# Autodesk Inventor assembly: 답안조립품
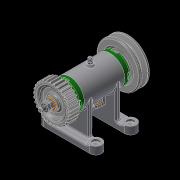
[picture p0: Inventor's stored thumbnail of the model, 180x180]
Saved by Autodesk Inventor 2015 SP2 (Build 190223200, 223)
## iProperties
Created: 2015-11
Part Number: 답안조립품
Document SubType Name: Assembly
Designer: AMC
Author: AMC
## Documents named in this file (15)
- C:\Users\AMC\Desktop\451109v1023\답안조립품.iam
- C:\Users\AMC\Desktop\451109v1023\본체.ipt
- C:\Users\AMC\Desktop\451109v1023\베어링 15 x 32 x 9.ipt
- C:\Users\AMC\Desktop\451109v1023\커버.ipt
- C:\Users\AMC\Desktop\451109v1023\오일 실 15 25 7.ipt
- C:\Users\AMC\Desktop\451109v1023\축.ipt
- C:\Users\AMC\Desktop\451109v1023\키 3 x 3 x 12.ipt
- C:\Users\AMC\Desktop\451109v1023\볼트 M4 x 12.ipt
- C:\Users\AMC\Desktop\451109v1023\V벨트풀리.ipt
- C:\Users\AMC\Desktop\451109v1023\스퍼기어.ipt
- C:\Users\AMC\Desktop\451109v1023\니플 M 6 x 0.75.ipt
- C:\Users\AMC\Desktop\451109v1023\볼트 M 6 x 8.ipt
- C:\Users\AMC\Desktop\451109v1023\와셔 6x11.5.ipt
- C:\Users\AMC\Desktop\451109v1023\와셔 8x17.ipt
- C:\Users\AMC\Desktop\451109v1023\너트 M 8.ipt
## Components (11 placed, 3 different names)
1. KS B 2023 6002 - 15 x 32 x 9:1
2. KS B 2023 6002 - 15 x 32 x 9:2
3. V벨트풀리:1 — 플러쉬:2
4. ISO 4762 M4 x 12:5
5. ISO 4762 M4 x 12:6
6. ISO 4762 M4 x 12:7
7. ISO 4762 M4 x 12:8
8. ISO 4762 M4 x 12:1
9. ISO 4762 M4 x 12:2
10. ISO 4762 M4 x 12:3
11. ISO 4762 M4 x 12:4
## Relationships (1: Flush 1)
- 플러쉬:2 [Flush]: V벨트풀리:1
